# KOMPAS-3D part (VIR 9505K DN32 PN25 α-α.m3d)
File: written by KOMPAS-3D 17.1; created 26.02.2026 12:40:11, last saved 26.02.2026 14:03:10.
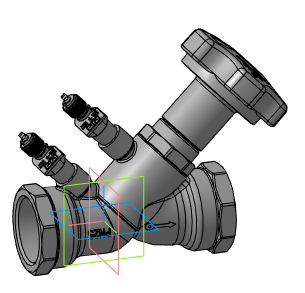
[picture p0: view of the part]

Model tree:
1. Операция без истории:4  (labels: VIR 9505K DN32 PN25 р-р)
